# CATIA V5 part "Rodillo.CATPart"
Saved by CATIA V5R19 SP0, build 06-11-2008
Part number: Rodillo
Publications: "Plane.1"
Material "Iron": density 7870 kg/m3, Young's modulus 1.2e+11 Pa, Poisson ratio 0.291, thermal expansion 1.21e-05 1/K
Bounding box of the stored display mesh (mm): x -19.05 to 19.05, y -25.4 to 25.4, z -25.215 to 25.215
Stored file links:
  E:\Luis\Dropbox\3DIT\Parking\planos\cat 3 dit park8\Cadena\Rodillo.CATPart
  E:\Luis\Dropbox\3DIT\Parking\planos\cat 3 dit park8\Cadena\Eslabon de Cadena.........................................CATProduct
  E:\Luis\Dropbox\3DIT\Parking\planos\cat 3 dit park8\Cadena\Pin Abierto.CATPart
  C:\Program Files (x86)\Dassault Systemes\B19\intel_a\startup\materials\Catalog.CATMaterial
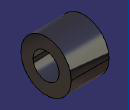
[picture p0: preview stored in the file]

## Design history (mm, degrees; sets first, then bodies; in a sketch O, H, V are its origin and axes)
Parameters
  d1 = 50.8
  d2 = 26.4
  b1 = 38.1
AxisSystem1: origin (0, 0, 0), X (1, 0, 0), Y (0, 1, 0), Z (0, 0, 1)
Set1
  Plane1: stored without definition
Set2
  Plane2: type Offset, Offset 0, RefPlane Plane1
Body1 (main body), material "Iron"
  Sketch1 on Plane1, origin (0, 0, 0), H (0, 1, 0), V (0, 0, 1)
    circle A1 centre (0, 0) radius 13.2
    circle A2 centre (0, 0) radius 25.4
    radius A2 = 25.4 {= d1 /2/1000}
    radius A1 = 13.2 {= d2 /2/1000}
  Pad1: profile Sketch1, direction (1, 0, 0), length 19.05 {= b1 /2/1000}, mirrored extent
